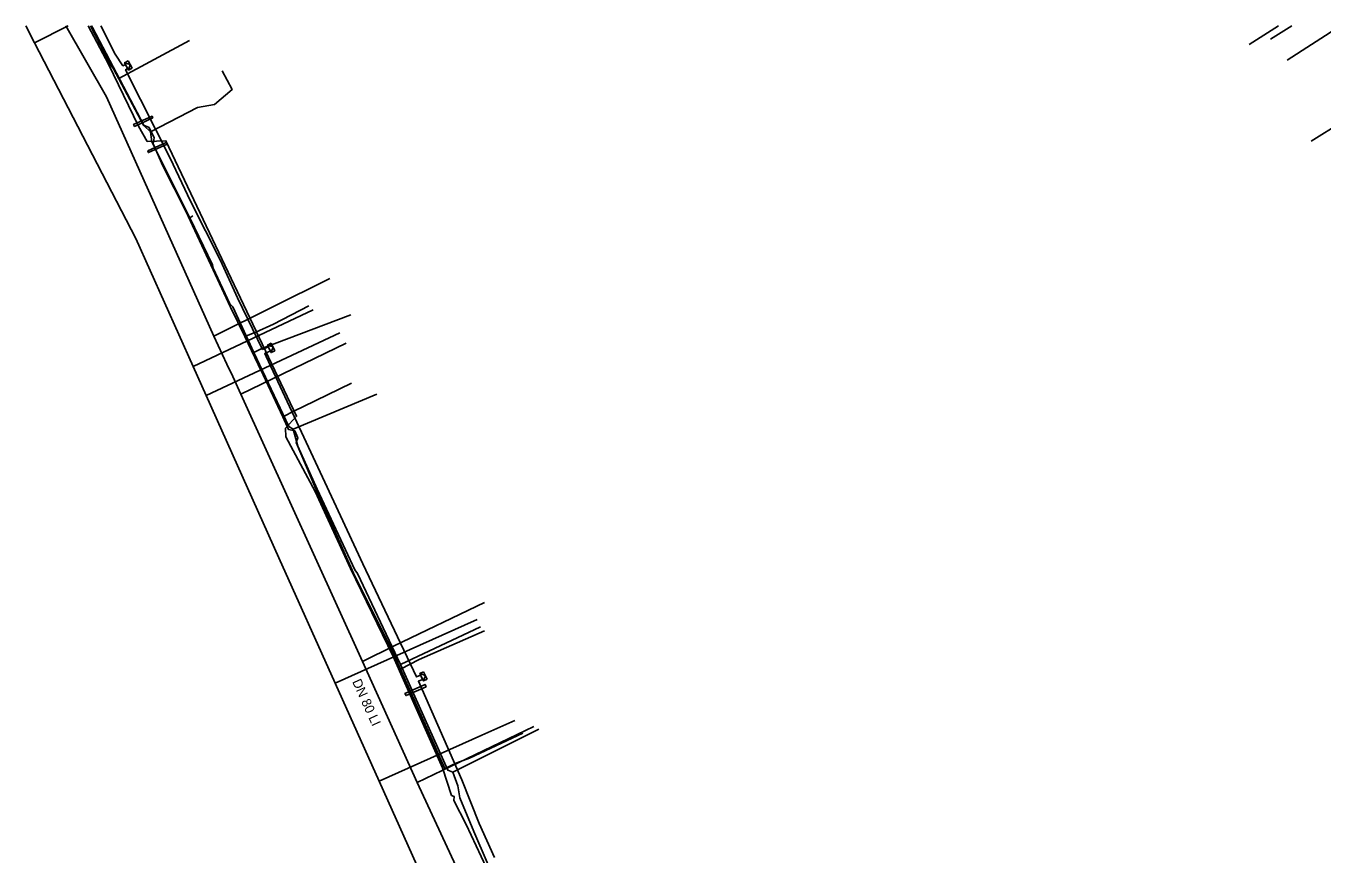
# Model space of a CAD drawing. Extents: x -600391 to -599491, y -1160176 to -1159402.
# Drawn here: x -600146.3 to -600036.7, y -1159471.8 to -1159401.8 of the extents above; entities that cross this region are included whole.
import ezdxf

# ---------------------------------------------------------------- set-up
doc = ezdxf.new("R2010")
doc.units = 0
for name, color, linetype in [('31', 7, 'Continuous'), ('CETIN_linie', 7, 'Continuous'), ('UPC_ok_linie', 7, 'Continuous'), ('Vrstva 13', 7, 'Continuous'), ('Vrstva 15', 7, 'Continuous'), ('Vrstva 16', 7, 'Continuous'), ('Vrstva 3', 7, 'Continuous'), ('Vrstva 42', 7, 'Continuous'), ('Vrstva 43', 7, 'Continuous'), ('Vrstva 55', 7, 'Continuous')]:
    doc.layers.add(name, color=color, linetype=linetype)

# ---------------------------------------------------------------- blocks, each defined once
blk = doc.blocks.new('NN630')
at = {"layer": '31'}
for points in [[(0, -0.7), (-0.7, 0)], [(-0.7, -0.7), (-0.7, 0), (0.7, 0), (0.7, -0.7)], [(-0.7, -0.7), (0.7, -0.7)], [(0, -0.7), (0.7, 0)]]:
    blk.add_lwpolyline(points, dxfattribs=at)

msp = doc.modelspace()

# ---------------------------------------------------------------- linework, layer by layer
at = {"layer": 'CETIN_linie'}
for points in [[(-600132.47, -1159417.99), (-600135.68, -1159411.56), (-600135.79, -1159410.72), (-600136.33, -1159410.22), (-600140.71, -1159401.9), (-600140.78, -1159401.77)], [(-600135.79, -1159410.72), (-600131.82, -1159408.67), (-600130.39, -1159408.42), (-600128.9, -1159407.16), (-600129.75, -1159405.57)], [(-600030.03, -1159408.56), (-600030.79, -1159409.07), (-600031.49, -1159409.49), (-600032.4, -1159408.25), (-600037.64, -1159411.53)], [(-600132.47, -1159417.99), (-600132.22, -1159417.82)], [(-600103.74, -1159480.71), (-600107.33, -1159472.52), (-600108.47, -1159469.92), (-600109.65, -1159467.05), (-600109.8, -1159466.05), (-600110.22, -1159464.89), (-600110.66, -1159464.72), (-600114.67, -1159455.79), (-600118.3, -1159448.08), (-600118.52, -1159447.78), (-600121.71, -1159440.94), (-600123.33, -1159437.31), (-600123.72, -1159435.89), (-600124.11, -1159435.65), (-600127.06, -1159429.4), (-600128.85, -1159425.52), (-600129.08, -1159425.29), (-600130.5, -1159422.26), (-600130.55, -1159421.99), (-600132.47, -1159417.99)], [(-600127.06, -1159429.4), (-600126.37, -1159429.05), (-600118.86, -1159426.21)], [(-600123.72, -1159435.89), (-600116.67, -1159432.91)], [(-600114.67, -1159455.79), (-600107.88, -1159452.6)], [(-600110.22, -1159464.89), (-600102.95, -1159461.24)]]:
    msp.add_lwpolyline(points, dxfattribs=at)
at = {"layer": 'UPC_ok_linie'}
for p, q in [((-600041.1, -1159402.88), (-600039.29, -1159401.77)), ((-600138.48, -1159406.21), (-600132.5, -1159403.01)), ((-600122.42, -1159425.44), (-600125.39, -1159427)), ((-600118.8, -1159431.99), (-600122.87, -1159433.97)), ((-600107.56, -1159452.93), (-600113.07, -1159455.36)), ((-600104.32, -1159461.59), (-600108.82, -1159463.7))]:
    msp.add_line(p, q, dxfattribs=at)
for points in [[(-600140.88, -1159401.77), (-600139.16, -1159405.08), (-600138.92, -1159405.4), (-600136.38, -1159410.15), (-600135.92, -1159410.35), (-600135.48, -1159411.23), (-600135.56, -1159411.73), (-600134.76, -1159413.6), (-600132.82, -1159417.45), (-600130.71, -1159421.97), (-600129.04, -1159425.57), (-600127.81, -1159428.03), (-600126.68, -1159430.41), (-600126.27, -1159431.28), (-600124.6, -1159434.83), (-600124.14, -1159435.9), (-600123.59, -1159436.03), (-600123.34, -1159436.62), (-600123.48, -1159437), (-600121.9, -1159440.73), (-600118.63, -1159448.07), (-600115.21, -1159454.89), (-600114.83, -1159455.8), (-600111.73, -1159462.76), (-600111.32, -1159463.65), (-600110.91, -1159464.59)], [(-600127.81, -1159428.03), (-600126.89, -1159427.66), (-600125.39, -1159427)], [(-600124.6, -1159434.83), (-600123.61, -1159434.32), (-600122.87, -1159433.97)], [(-600114.67, -1159456.19), (-600113.07, -1159455.36)], [(-600110.91, -1159464.59), (-600109.89, -1159464.1), (-600108.82, -1159463.7)]]:
    msp.add_lwpolyline(points, dxfattribs=at)
at = {"layer": 'Vrstva 13'}
for p, q in [((-600040.42, -1159401.77), (-600042.88, -1159403.35)), ((-600130.43, -1159428.01), (-600120.62, -1159423.14)), ((-600128.16, -1159432.93), (-600119.26, -1159428.59)), ((-600113.25, -1159465.76), (-600103.38, -1159461.02))]:
    msp.add_line(p, q, dxfattribs=at)
for points in [[(-600129.35, -1159430.38), (-600130.43, -1159428.01), (-600139.53, -1159407.76), (-600142.96, -1159401.77)], [(-600100.12, -1159494.2), (-600104.87, -1159483.8), (-600113.25, -1159465.76), (-600117.88, -1159455.52), (-600128.16, -1159432.93), (-600128.85, -1159431.42), (-600129.35, -1159430.38)], [(-600117.88, -1159455.52), (-600115.18, -1159454.21), (-600107.54, -1159450.55)]]:
    msp.add_lwpolyline(points, dxfattribs=at)
at = {"layer": 'Vrstva 16'}
for p, q in [((-600145.61, -1159403.21), (-600142.75, -1159401.77)), ((-600035.17, -1159401.77), (-600039.67, -1159404.66))]:
    msp.add_line(p, q, dxfattribs=at)
for points in [[(-600097.75, -1159502.22), (-600104.37, -1159493.89), (-600111.18, -1159477.41), (-600116.46, -1159465.65), (-600120.17, -1159457.36), (-600124.94, -1159446.75), (-600131.08, -1159433.04), (-600132.18, -1159430.58), (-600137.03, -1159419.75), (-600145.61, -1159403.21), (-600146.33, -1159401.77)], [(-600132.18, -1159430.58), (-600122.03, -1159425.79)], [(-600131.08, -1159433.04), (-600119.79, -1159427.72)], [(-600120.17, -1159457.36), (-600113.01, -1159454.15), (-600108.17, -1159451.98)], [(-600116.46, -1159465.65), (-600107.79, -1159461.76), (-600105, -1159460.51)]]:
    msp.add_lwpolyline(points, dxfattribs=at)
at = {"layer": 'Vrstva 3'}
for points in [[(-600135.6, -1159409.55), (-600137.15, -1159410.27), (-600137.23, -1159410.1), (-600135.67, -1159409.41)], [(-600134.39, -1159411.78), (-600135.97, -1159412.49), (-600136.02, -1159412.34), (-600134.46, -1159411.63)], [(-600112.5, -1159457.67), (-600114.18, -1159458.41), (-600114.28, -1159458.24), (-600112.58, -1159457.47)]]:
    msp.add_lwpolyline(points, close=True, dxfattribs=at)
at = {"layer": 'Vrstva 42'}
msp.add_lwpolyline([(-600106.7, -1159472.11), (-600108, -1159469.22), (-600109.47, -1159465.54), (-600113.02, -1159457.45), (-600113.14, -1159457.2), (-600112.79, -1159457.04), (-600112.87, -1159456.86), (-600112.96, -1159456.68), (-600113.31, -1159456.84), (-600117.85, -1159447.28), (-600121.07, -1159440.37), (-600126.03, -1159429.72), (-600126.14, -1159429.49), (-600125.66, -1159429.26), (-600125.75, -1159429.08), (-600125.84, -1159428.9), (-600126.32, -1159429.13), (-600128.45, -1159424.77), (-600129.88, -1159421.6), (-600132.42, -1159416.59), (-600134.14, -1159412.96), (-600137.91, -1159405.48), (-600137.73, -1159405.38), (-600137.82, -1159405.2), (-600137.91, -1159405.03), (-600138.13, -1159405.14), (-600138.79, -1159404.16), (-600140, -1159401.77)], dxfattribs=at)
at = {"layer": 'Vrstva 55'}
for points in [[(-600136.09, -1159411.55), (-600136.8, -1159410.25), (-600139.34, -1159405.01), (-600141.07, -1159401.77)], [(-600124.39, -1159435.79), (-600123.45, -1159434.78), (-600134.5, -1159411.48), (-600136.09, -1159411.55)], [(-600097.35, -1159493.11), (-600098.54, -1159493.56), (-600099.32, -1159491.78), (-600099.23, -1159491.68), (-600099.09, -1159491.18), (-600099.67, -1159490.22), (-600100.11, -1159490.08), (-600100.91, -1159487.9), (-600104.48, -1159479.24), (-600107.41, -1159472.94), (-600109.1, -1159469.32), (-600110.15, -1159467.28), (-600110.13, -1159466.94), (-600110.34, -1159466.86), (-600111.11, -1159464.52), (-600115.27, -1159455.11), (-600118.88, -1159447.66), (-600121.87, -1159441.15), (-600124.36, -1159436.52), (-600124.39, -1159435.79)]]:
    msp.add_lwpolyline(points, dxfattribs=at)

# ---------------------------------------------------------------- block references
at = {"layer": 'Vrstva 43'}
for p, xscale, yscale, rotation in [((-600137.82, -1159405.2), 0.5, 0.5, 117.99999999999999), ((-600125.75, -1159429.08), 0.5000000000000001, 0.5000000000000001, 116.00000000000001), ((-600112.87, -1159456.86), 0.5000000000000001, 0.5, 115)]:
    msp.add_blockref('NN630', p, dxfattribs=dict(at, xscale=xscale, yscale=yscale, rotation=rotation))

# ---------------------------------------------------------------- texts
at = {"layer": 'Vrstva 15'}
msp.add_text('DN 80 LI', height=0.8, rotation=294.3284, dxfattribs=at).set_placement((-600118.76, -1159457.23))

doc.saveas('drawing.dxf')
